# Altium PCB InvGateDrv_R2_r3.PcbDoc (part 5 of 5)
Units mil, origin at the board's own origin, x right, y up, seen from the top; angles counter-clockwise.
Board outline 6245 x 2850 mil, 4 copper layers (Top Layer, Power, Ground, Bottom Layer), stack 104.204 mil thick; 409 components, 181 nets, 1050 pads, 683 vias.
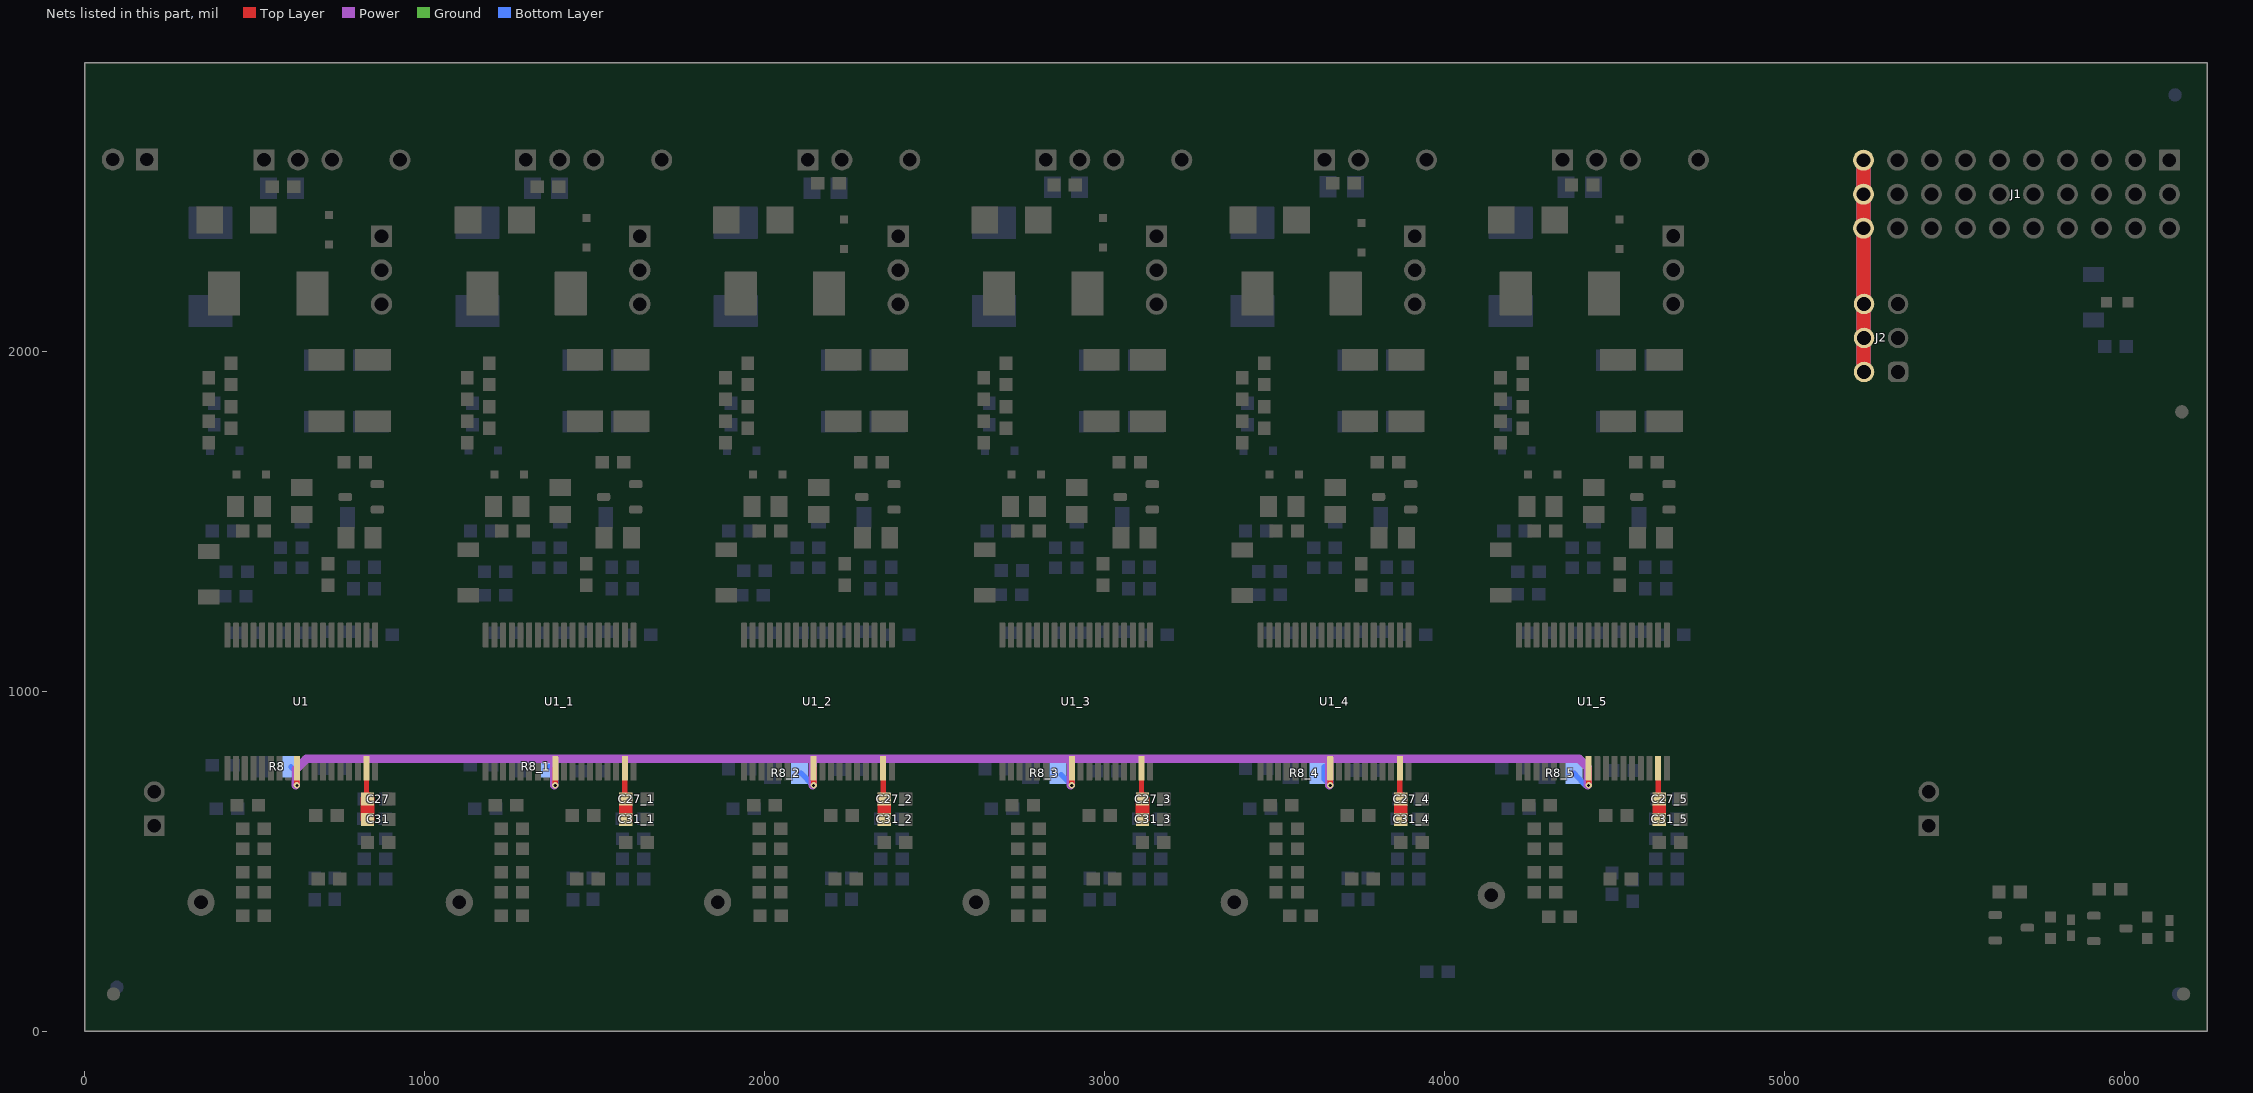
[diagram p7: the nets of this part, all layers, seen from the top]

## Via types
v1: diameter 19, hole 9, Top Layer to Bottom Layer, tented both sides, 617 vias
v2: diameter 20, hole 10, Top Layer to Bottom Layer, tented both sides, 66 vias

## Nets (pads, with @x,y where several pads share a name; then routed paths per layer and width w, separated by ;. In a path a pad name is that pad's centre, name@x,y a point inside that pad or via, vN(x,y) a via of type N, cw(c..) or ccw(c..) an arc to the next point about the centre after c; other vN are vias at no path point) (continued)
VCC1_3V3: R8.2 R8_1.2 R8_2.2 R8_3.2 R8_4.2 R8_5.2 U1.9 U1_1.9 U1_2.9 U1_3.9 U1_4.9 U1_5.9 | length 4872.4
  Top Layer w16: v1(624.57,723.98) U1.9@624.57,774.17 ; v1(1384.56,723.98) U1_1.9@1384.56,774.18 ; v1(2144.57,723.98) U1_2.9@2144.57,774.17 ; v1(2904,724) 2904,773.61 U1_3.9@2904.57,774.17 ; v1(3664.57,723.98) U1_4.9@3664.57,774.17 ; v1(4424.56,723.98) U1_5.9@4424.56,774.18
  Power w25: v1@621.78,723.98 621.78,771.39 652.13,801.73 1390.08,801.73 ; v1@1381.78,723.98 1381.78,793.43 1390.08,801.73 ; v1@2141.78,723.98 2141.78,793.44 2150.08,801.73 ; 2898.35,795 2901.78,791.56 v1@2901.78,723.98 ; 3658.35,795 3661.78,791.56 v1@3661.78,723.98 ; v1@4421.78,723.98 4421.78,776.96 4397.01,801.73 2150.08,801.73 ; 1390.08,801.73 2150.08,801.73
  Bottom Layer w16: R8.2@607.09,778.11 624.57,760.63 v1(624.57,723.98) ; R8_1.2@1367.08,778.11 1384.56,760.63 v1(1384.56,723.98) ; R8_2.2@2106.94,760 2142.96,723.98 v1(2144.57,723.98) ; R8_3.2@2873.07,755 2904.57,723.5 2904.07,724 v1(2904,724) ; R8_4.2@3647.09,778.11 3647.09,741.46 v1(3664.57,723.98) ; R8_5.2@4381.93,760 4407.08,731.89 4414.99,723.98 v1(4424.56,723.98)
VCC2: J1.28 J1.29 J1.30 J2.2 J2.4 J2.6 | length 2494.3
  Top Layer w40: J1.28@5233.35,2562.88 J1.29@5233.35,2462.88 J1.30@5233.35,2362.88 5233.35,1941.65 J2.2@5235,1940
  Power w40: J1.28@5233.35,2562.88 J1.29@5233.35,2462.88 J1.30@5233.35,2362.88 5233.35,1941.65 J2.2@5235,1940
  Ground w40: J1.28@5233.35,2562.88 J1.29@5233.35,2462.88 J1.30@5233.35,2362.88 5233.35,1941.65 J2.2@5235,1940
  Bottom Layer w40: J1.28@5233.35,2562.88 J1.29@5233.35,2462.88 J1.30@5233.35,2362.88 5233.35,1941.65 J2.2@5235,1940
VREG: C27.1 C31.1 U1.17 | length 151.8
  Top Layer w16: U1.17@829.29,774.17 829.29,686.57 C27.1@832.24,683.62
  Top Layer w40: C31.1@832.24,623.58 C27.1@832.24,683.62
VREG_1: C27_1.1 C31_1.1 U1_1.17 | length 151.8
  Top Layer w16: U1_1.17@1589.29,774.18 1589.29,686.58 C27_1.1@1592.24,683.62
  Top Layer w40: C31_1.1@1592.24,623.58 C27_1.1@1592.24,683.62
VREG_2: C27_2.1 C31_2.1 U1_2.17 | length 151.8
  Top Layer w16: U1_2.17@2349.29,774.17 2349.29,686.57 C27_2.1@2352.24,683.62
  Top Layer w40: C31_2.1@2352.24,623.58 C27_2.1@2352.24,683.62
VREG_3: C27_3.1 C31_3.1 U1_3.17 | length 151.8
  Top Layer w16: U1_3.17@3109.29,774.17 3109.29,686.57 C27_3.1@3112.24,683.62
  Top Layer w40: C31_3.1@3112.24,623.58 C27_3.1@3112.24,683.62
VREG_4: C27_4.1 C31_4.1 U1_4.17 | length 151.8
  Top Layer w16: U1_4.17@3869.29,774.17 3869.29,686.57 C27_4.1@3872.24,683.62
  Top Layer w40: C31_4.1@3872.24,623.58 C27_4.1@3872.24,683.62
VREG_5: C27_5.1 C31_5.1 U1_5.17 | length 151.8
  Top Layer w16: U1_5.17@4629.29,774.18 4629.29,686.58 C27_5.1@4632.24,683.63
  Top Layer w40: C31_5.1@4632.24,623.59 C27_5.1@4632.24,683.63
pads on no net: FID1.1 FID2.1 FID3.1 FID4.1 FID5.1 FID6.1 J1.1 J1.22 J1.23 J3.1 J3.2 J6.1 J6.2 R22_1.2 R22_2.2 R22_3.2 R22_4.2 R22_5.2 R25_1.2 R25_2.2 R25_3.2 R25_4.2 R25_5.2 U1.2 U1.3 U1.4 U1.5 U1_1.2 U1_1.3 U1_1.4 U1_1.5 U1_2.2 U1_2.3 U1_2.4 U1_2.5 U1_3.2 U1_3.3 U1_3.4 U1_3.5 U1_4.2 U1_4.3 U1_4.4 U1_4.5 U1_5.2 U1_5.3 U1_5.4 U1_5.5

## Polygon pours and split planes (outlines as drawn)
GND on Ground "GROUND_GND_P118" (solid, remove dead copper, pour order 118): 5885.83,2690 5985.83,2590 5985.83,421.52 5694.31,130 4825.83,130 4639.02,316.8 4639.66,704.64 4708.46,778.51 5177.67,778.5 5224.17,825 5224.17,1844 5245.98,1865.81 5360,1865.81 5385,1890 5385,2610 5465,2690
GND on Ground "GROUND_GND_P002" (solid, remove dead copper, pour order 2): 893.27,792.87 932.64,753.5 932.64,94.06 873.58,35 381.46,35 332.24,84.21 332.24,753.5 371.61,792.87
GND on Ground "GROUND_GND_P022" (solid, remove dead copper, pour order 22): 1653.26,792.88 1692.63,753.51 1692.63,94.06 1633.58,35 1141.45,35 1092.24,84.21 1092.24,753.51 1131.61,792.88
GND on Ground "GROUND_GND_P038" (solid, remove dead copper, pour order 38): 2413.27,792.87 2452.64,753.5 2452.64,94.05 2393.58,35 1901.46,35 1852.24,84.21 1852.24,753.5 1891.61,792.87
GND on Ground "GROUND_GND_P054" (solid, remove dead copper, pour order 54): 3173.27,792.87 3212.64,753.5 3212.64,94.06 3153.58,35 2661.46,35 2612.24,84.21 2612.24,753.5 2651.61,792.87
GND on Ground "GROUND_GND_P086" (solid, remove dead copper, pour order 86): 3933.27,792.87 3972.64,753.5 3972.64,94.05 3913.58,35 3421.46,35 3372.24,84.21 3372.24,753.5 3411.61,792.87
GND on Ground "GROUND_GND_P102" (solid, remove dead copper, pour order 102): 4693.26,792.88 4732.63,753.51 4732.63,94.06 4673.58,35 4181.45,35 4132.24,84.22 4132.24,753.51 4171.61,792.88
no net on Ground "GROUND_NONET_P100" (solid, remove dead copper, pour order 100): 4693.26,1127.52
ISO_GND_5 on Ground "GROUND_ISO_GND_5_P098" (solid, remove dead copper, pour order 98): 4210.18,1137.37 4667.81,1137.37 4728.62,1198.18 4728.62,2332.33 4673.58,2387.37 4201.14,2387.37 4142.08,2328.31 4142.08,1197.56
no net on Ground "GROUND_NONET_P084" (solid, remove dead copper, pour order 84): 3933.27,1127.52
ISO_GND_4 on Ground "GROUND_ISO_GND_4_P082" (solid, remove dead copper, pour order 82): 3450.18,1137.36 3907.81,1137.36 3968.62,1198.17 3968.62,2332.32 3913.58,2387.36 3441.14,2387.36 3382.09,2328.31 3382.09,1197.56
no net on Ground "GROUND_NONET_P052" (solid, remove dead copper, pour order 52): 3173.27,1127.52
ISO_GND_3 on Ground "GROUND_ISO_GND_3_P050" (solid, remove dead copper, pour order 50): 2690.18,1137.36 3147.81,1137.36 3208.62,1198.17 3208.62,2332.32 3153.58,2387.36 2681.14,2387.36 2622.09,2328.31 2622.09,1197.56
no net on Ground "GROUND_NONET_P036" (solid, remove dead copper, pour order 36): 2413.27,1127.52
ISO_GND_2 on Ground "GROUND_ISO_GND_2_P034" (solid, remove dead copper, pour order 34): 1930.18,1137.36 2387.81,1137.36 2448.62,1198.17 2448.62,2332.32 2393.58,2387.36 1921.14,2387.36 1862.09,2328.31 1862.09,1197.56
no net on Ground "GROUND_NONET_P020" (solid, remove dead copper, pour order 20): 1653.26,1127.52
ISO_GND_1 on Ground "GROUND_ISO_GND_1_P018" (solid, remove dead copper, pour order 18): 1170.17,1137.36 1627.81,1137.36 1688.62,1198.17 1688.62,2332.33 1633.58,2387.36 1161.14,2387.36 1102.08,2328.31 1102.08,1197.56
ISO_GND on Ground "GROUND_ISO_GND_P014" (solid, remove dead copper, pour order 14): 410.18,1137.36 867.81,1137.36 928.62,1198.17 928.62,2332.32 873.58,2387.36 401.14,2387.36 342.09,2328.31 342.09,1197.56
no net on Ground "GROUND_NONET_P012" (solid, remove dead copper, pour order 12): 893.27,1127.52
ISO_GND_5 on Top Layer "TOP_LAYER_ISO_GND_5_P144" (solid, remove dead copper, pour order 144): 4546.22,1232.88 4553.34,1240 4603.34,1240 4613.34,1230 4612.56,1229.22 4612.56,1143.86 4603.7,1135 4553.34,1135 4546.22,1142.13
ISO_GND_4 on Top Layer "TOP_LAYER_ISO_GND_4_P142" (solid, remove dead copper, pour order 142): 3786.22,1232.87 3793.35,1240 3843.35,1240 3853.35,1230 3852.56,1229.21 3852.56,1143.86 3843.7,1135 3793.35,1135 3786.22,1142.13
ISO_GND_3 on Top Layer "TOP_LAYER_ISO_GND_3_P140" (solid, remove dead copper, pour order 140): 3026.22,1232.87 3033.35,1240 3083.35,1240 3093.35,1230 3092.56,1229.21 3092.56,1143.86 3083.7,1135 3033.35,1135 3026.22,1142.13
ISO_GND_2 on Top Layer "TOP_LAYER_ISO_GND_2_P138" (solid, remove dead copper, pour order 138): 2266.22,1232.87 2273.35,1240 2323.35,1240 2333.35,1230 2332.56,1229.21 2332.56,1143.86 2323.7,1135 2273.35,1135 2266.22,1142.13
ISO_GND_1 on Top Layer "TOP_LAYER_ISO_GND_1_P136" (solid, remove dead copper, pour order 136): 1506.22,1232.88 1513.34,1240 1563.34,1240 1573.34,1230 1572.55,1229.21 1572.55,1143.86 1563.7,1135 1513.34,1135 1506.22,1142.13
ISO_GND on Top Layer "TOP_LAYER_ISO_GND_P134" (solid, remove dead copper, pour order 134): 746.22,1232.87 753.35,1240 803.35,1240 813.35,1230 812.56,1229.21 812.56,1143.86 803.7,1135 753.35,1135 746.22,1142.13
VCC1 on Top Layer "TOP_LAYER_VCC1_P132" (solid, remove dead copper, pour order 132): 4395.98,361.93 4417.4,383.35 4417.4,449.22 4440.12,471.93 4632.75,471.93 4657.4,447.29 4657.4,336.93 4628.97,308.51 4362.24,308.51 4352.4,318.35 4352.4,356.93 4357.4,361.93
VCC1 on Top Layer "TOP_LAYER_VCC1_P128" (solid, remove dead copper, pour order 128): 3633.19,365 3654.61,386.42 3654.61,452.28 3677.32,475 3869.96,475 3894.61,450.35 3894.61,340 3866.18,311.57 3599.45,311.57 3589.61,321.42 3589.61,360 3594.61,365
VCC1 on Top Layer "TOP_LAYER_VCC1_P126" (solid, remove dead copper, pour order 126): 2831.93,365 2853.35,386.42 2853.35,452.28 2876.06,475 3068.7,475 3093.35,450.35 3093.35,340 3064.92,311.57 2798.19,311.57 2788.35,321.42 2788.35,360 2793.35,365
VCC1 on Top Layer "TOP_LAYER_VCC1_P124" (solid, remove dead copper, pour order 124): 2071.93,365 2093.35,386.42 2093.35,452.28 2116.06,475 2308.7,475 2333.35,450.35 2333.35,340 2304.92,311.57 2038.19,311.57 2028.35,321.42 2028.35,360 2033.35,365
VCC1 on Top Layer "TOP_LAYER_VCC1_P122" (solid, remove dead copper, pour order 122): 1311.92,365 1333.34,386.42 1333.34,452.29 1356.06,475 1548.7,475 1573.34,450.36 1573.34,340 1544.92,311.58 1278.18,311.58 1268.34,321.42 1268.34,360 1273.34,365
VCC1 on Top Layer "TOP_LAYER_VCC1_P120" (solid, remove dead copper, pour order 120): 551.93,365 573.35,386.42 573.35,452.28 596.06,475 788.7,475 813.35,450.35 813.35,340 784.92,311.57 518.19,311.57 508.35,321.42 508.35,360 513.35,365
VCC1 on Top Layer "Top Layer-VCC1" (solid, pour order 114): 5989.15,279.2 6013.35,255 6013.35,240 5993.35,220 5553.35,220 5538.35,235 5538.35,255 5562.55,279.2
GND on Top Layer "TOP_LAYER_GND_P110" (solid, pour order 110): 4703.11,812.56 4732.63,783.04 4732.63,526.15 4713.93,507.45 4684.41,507.45 4673.58,518.27 4673.58,723.98 4653.89,743.67 4653.89,805.28 4661.18,812.56
GND on Top Layer "TOP_LAYER_GND_P108" (solid, remove dead copper, pour order 108): 4208.34,810.3 4212.26,810.3 4159.46,810.3 4132.24,783.08 4132.24,438.55 4171.61,399.18 4270.04,399.18 4289.72,418.86 4289.72,785.6 4264.72,810.6 4161.77,810.3
ISO_VCC_5 on Top Layer "TOP_LAYER_ISO_VCC_5_P106" (solid, remove dead copper, pour order 106): 4250.35,1292.58 4228.8,1315.54 4142.81,1315.54 4132.24,1307.72 4132.24,1157.05 4160.22,1129.49 4235.59,1129.49 4250.35,1144.26
ISO_VEE_5 on Top Layer "TOP_LAYER_ISO_VEE_5_P104" (solid, pour order 104): 4682.44,1364.89 4652.91,1335.36 4652.91,1146.78 4661.18,1138.51 4713.93,1138.51 4728.34,1152.92 4728.34,1349.49 4712.95,1364.89
GND on Top Layer "TOP_LAYER_GND_P094" (solid, pour order 94): 3943.11,812.56 3972.64,783.03 3972.64,526.14 3953.94,507.44 3924.41,507.44 3913.58,518.27 3913.58,723.98 3893.9,743.66 3893.9,805.28 3901.18,812.56
GND on Top Layer "TOP_LAYER_GND_P092" (solid, remove dead copper, pour order 92): 3448.35,810.3 3452.26,810.3 3399.47,810.3 3372.24,783.08 3372.24,438.54 3411.61,399.17 3510.04,399.17 3529.72,418.86 3529.72,785.59 3504.72,810.59 3401.77,810.3
ISO_VCC_4 on Top Layer "TOP_LAYER_ISO_VCC_4_P090" (solid, remove dead copper, pour order 90): 3490.35,1292.58 3468.8,1315.53 3389.02,1315.53 3372.24,1303.13 3372.24,1157.05 3400.22,1129.49 3475.59,1129.49 3490.35,1144.25
ISO_VEE_4 on Top Layer "TOP_LAYER_ISO_VEE_4_P088" (solid, pour order 88): 3922.44,1364.88 3892.91,1335.35 3892.91,1146.77 3901.18,1138.5 3953.94,1138.5 3968.35,1152.91 3968.35,1349.49 3952.95,1364.88
GND on Top Layer "TOP_LAYER_GND_P062" (solid, pour order 62): 3183.11,812.56 3212.64,783.03 3212.64,526.14 3193.94,507.44 3164.41,507.44 3153.58,518.27 3153.58,723.98 3133.9,743.66 3133.9,805.28 3141.18,812.56
GND on Top Layer "TOP_LAYER_GND_P060" (solid, remove dead copper, pour order 60): 2688.35,810.3 2692.26,810.3 2639.47,810.3 2612.24,783.08 2612.24,438.54 2651.61,399.17 2750.04,399.17 2769.72,418.86 2769.72,785.59 2744.72,810.59 2641.77,810.3
ISO_VCC_3 on Top Layer "TOP_LAYER_ISO_VCC_3_P058" (solid, remove dead copper, pour order 58): 2730.35,1292.58 2708.8,1315.54 2622.81,1315.54 2612.24,1307.72 2612.24,1157.05 2640.22,1129.49 2715.59,1129.49 2730.35,1144.25
ISO_VEE_3 on Top Layer "TOP_LAYER_ISO_VEE_3_P056" (solid, pour order 56): 3162.44,1364.88 3132.91,1335.35 3132.91,1146.77 3141.18,1138.5 3193.94,1138.5 3208.35,1152.91 3208.35,1349.49 3192.95,1364.88
GND on Top Layer "TOP_LAYER_GND_P046" (solid, pour order 46): 2423.11,812.56 2452.64,783.03 2452.64,526.14 2433.94,507.44 2404.41,507.44 2393.58,518.27 2393.58,723.98 2373.9,743.66 2373.9,805.28 2381.18,812.56
GND on Top Layer "TOP_LAYER_GND_P044" (solid, remove dead copper, pour order 44): 1928.35,810.3 1932.26,810.3 1879.47,810.3 1852.24,783.08 1852.24,438.54 1891.61,399.17 1990.04,399.17 2009.72,418.86 2009.72,785.59 1984.72,810.59 1881.77,810.3
ISO_VCC_2 on Top Layer "TOP_LAYER_ISO_VCC_2_P042" (solid, remove dead copper, pour order 42): 1970.35,1292.58 1948.8,1315.53 1880.22,1315.53 1852.24,1294.84 1852.24,1157.05 1880.22,1129.49 1955.59,1129.49 1970.35,1144.25
ISO_VEE_2 on Top Layer "TOP_LAYER_ISO_VEE_2_P040" (solid, pour order 40): 2402.44,1364.88 2372.91,1335.35 2372.91,1146.77 2381.18,1138.5 2433.94,1138.5 2448.35,1152.91 2448.35,1349.49 2432.95,1364.88
GND on Top Layer "TOP_LAYER_GND_P030" (solid, pour order 30): 1663.11,812.56 1692.63,783.03 1692.63,526.14 1673.93,507.44 1644.41,507.44 1633.58,518.27 1633.58,723.98 1613.89,743.66 1613.89,805.28 1621.18,812.56
GND on Top Layer "TOP_LAYER_GND_P028" (solid, remove dead copper, pour order 28): 1157.7,810.3 1172.26,810.3 1119.46,810.3 1092.24,783.08 1092.24,438.55 1131.61,399.18 1230.04,399.18 1249.72,418.86 1249.72,785.59 1224.72,810.59 1121.77,810.3
ISO_VCC_1 on Top Layer "TOP_LAYER_ISO_VCC_1_P026" (solid, remove dead copper, pour order 26): 1210.35,1292.58 1188.79,1315.54 1109.02,1315.54 1092.24,1303.13 1092.24,1157.05 1120.22,1129.49 1195.59,1129.49 1210.35,1144.25
ISO_VEE_1 on Top Layer "TOP_LAYER_ISO_VEE_1_P024" (solid, pour order 24): 1642.44,1364.88 1612.91,1335.36 1612.91,1146.77 1621.18,1138.51 1673.93,1138.51 1688.34,1152.92 1688.34,1349.49 1672.95,1364.88
ISO_VEE on Top Layer "TOP_LAYER_ISO_VEE_P016" (solid, pour order 16): 882.44,1364.88 852.91,1335.35 852.91,1146.77 861.18,1138.5 913.94,1138.5 928.35,1152.91 928.35,1349.49 912.95,1364.88
ISO_VCC on Top Layer "TOP_LAYER_ISO_VCC_P010" (solid, remove dead copper, pour order 10): 450.35,1292.58 428.8,1315.54 360.22,1315.54 332.24,1294.84 332.24,1157.05 360.22,1129.49 435.59,1129.49 450.35,1144.25
GND on Top Layer "TOP_LAYER_GND_P006" (solid, remove dead copper, pour order 6): 408.35,810.3 412.26,810.3 359.47,810.3 332.24,783.08 332.24,438.54 371.61,399.17 470.04,399.17 489.72,418.86 489.72,785.59 464.72,810.59 361.77,810.3
GND on Top Layer "TOP_LAYER_GND_P004" (solid, pour order 4): 903.11,812.56 932.64,783.03 932.64,526.14 913.94,507.44 884.41,507.44 873.58,518.27 873.58,723.98 853.9,743.66 853.9,805.28 861.18,812.56
no net on Bottom Layer "Bottom Layer-No Net" (solid, pour order 116): 5463.35,2665
GND on Bottom Layer "BOTTOM_LAYER_GND_P112" (solid, remove dead copper, pour order 112): 4693.26,792.88 4732.63,753.51 4732.63,94.06 4673.58,35 4181.45,35 4132.24,84.22 4132.24,776.16 4148.96,792.88
GND on Bottom Layer "BOTTOM_LAYER_GND_P096" (solid, remove dead copper, pour order 96): 3933.27,792.87 3972.64,753.5 3972.64,94.05 3913.58,35 3421.46,35 3372.24,84.21 3372.24,767.24 3397.87,792.87
GND on Bottom Layer "BOTTOM_LAYER_GND_P064" (solid, remove dead copper, pour order 64): 3173.27,792.87 3212.64,753.5 3212.64,94.06 3153.58,35 2661.46,35 2612.24,84.21 2612.24,771.06 2634.06,792.87
GND on Bottom Layer "BOTTOM_LAYER_GND_P048" (solid, remove dead copper, pour order 48): 2413.27,792.87 2452.64,753.5 2452.64,94.05 2393.58,35 1901.46,35 1852.24,84.21 1852.24,767.24 1877.87,792.87
GND on Bottom Layer "BOTTOM_LAYER_GND_P032" (solid, remove dead copper, pour order 32): 1644.4,801.73 1692.63,753.51 1692.63,94.06 1633.58,35 1141.45,35 1092.24,84.21 1092.24,777.24 1116.73,801.73
GND on Bottom Layer "BOTTOM_LAYER_GND_P008" (solid, remove dead copper, pour order 8): 886.14,800 932.64,753.5 932.64,94.06 873.58,35 381.46,35 332.24,84.21 332.24,772.24 360,800

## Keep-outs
Keep-Out Layer:
  text ".Layer_Name" at 577,-858.49 h60

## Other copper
Top Layer:
  text ".Layer_Name" at 567,-858.49 h60
Power:
  text ".Layer_Name" at 577,-858.49 h60
Ground:
  text ".Layer_Name" at 572,-858.49 h60
Bottom Layer:
  text ".Layer_Name" at 577,-858.49 h60

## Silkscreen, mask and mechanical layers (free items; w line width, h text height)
Top Overlay:
  lines w20: 50,960 4975,960 4975,2810
  text "EGVDD C" at 679.91,2466.93 h40
  text "EG C" at 2284.66,2465 h40
  text "EGVDD C" at 4518.35,2462.8 h40
  text "EGVDD C" at 3005.84,2460.07 h40
  text "EG C" at 3810,2460 h40
  text "EGVDD C" at 1482.76,2458.94 h40
  text "GND A1" at 33.03,2449.36 h40
  text "LOW VOLTAGE" at 5056.11,2277.54 h80 r90
  text "HIGH VOLTAGE" at 4941.48,2269.81 h80 r90
  text "VEE GND VCC" at 3270,2010 h40 r90
  text "VEE GND VCC" at 4035,2010 h40 r90
  text "VEE GND VCC" at 4795,2010 h40 r90
  text "VEE GND VCC" at 1000,2005 h40 r90
  text "VEE GND VCC" at 2520,2005 h40 r90
  text "VEE GND VCC" at 1755,2002.44 h40 r90
  text "VCC1 on" at 6140,1962.75 h40 r90
  text "VCC2 GND" at 5114,1822.54 h40
  text "Danger High Voltage" at 195.5,1420 h110 r90
  text "LOW VOLTAGE" at 5055,1010 h80 r90
  text "HIGH VOLTAGE" at 4938.48,1005.87 h80 r90
  text "HIGH VOLTAGE" at 52.71,996.52 h80
  text "LOW VOLTAGE" at 53.09,877 h80
  text "'.PRJ_Number'.PCB_Rev" at 5813,838.9 h70 r90
  text "Inverter Gate Driver" at 5732,833.9 h120 r90
  text "FLT_HS" at 5795.16,410 h40 r90
  text "FLT_LS" at 6086.06,405 h40 r90
  text "CL" at 594.73,120 h80
  text "CH" at 1346.38,119 h80
  text "BL" at 2107.38,115 h80
  text "BH" at 2868.61,112 h80
  text "AL" at 3627.38,110 h80
  text "AH" at 4388.38,110 h80
  text ".Layer_Name" at 577,-858.49 h35
Bottom Overlay:
  lines w20: 50,960 131.36,960 ; 275,960 4975,960 4975,2810
  text "C   E G VDD" at 1707.67,2655 h40
  text "C    E G" at 2433.82,2655 h40
  text "C   E G VDD" at 3227.67,2655 h40
  text "C   E G VDD" at 935.35,2650 h40
  text "C    E G" at 3955,2650 h40
  text "C   E G VDD" at 4747.67,2650 h40
  text "LOW VOLTAGE" at 5053.11,2303.78 h80 r90
  text "HIGH VOLTAGE" at 4938.48,2296.05 h80 r90
  text "Danger High Voltage" at 123,1465 h110 r270
  text "Mech Sup Only" at 5350,1045.37 h30 r90
  text "HIGH VOLTAGE" at 952.31,996.52 h80
  text "HIGH VOLTAGE" at 4233.6,996.52 h80
  text "LOW VOLTAGE" at 960,877 h80
  text "LOW VOLTAGE" at 4240.57,875 h80
  text "Mech Sup Only" at 131.36,850 h30 r90
  text "CL" at 762.1,117.72 h80
  text "CH" at 1513.74,116.72 h80
  text "BL" at 2274.74,112.72 h80
  text "BH" at 3035.98,109.72 h80
  text "AL" at 3794.74,107.72 h80
  text "AH" at 4555.74,107.72 h80
  text ".Layer_Name" at 577,-858.49 h35
Top Paste:
  text ".Layer_Name" at 577,-858.49 h60
Bottom Paste:
  text ".Layer_Name" at 577,-858.49 h60
Top Solder:
  text ".Layer_Name" at 577,-858.49 h60
  text ".Layer_Name" at 577,-858.49 h60
Bottom Solder:
  text ".Layer_Name" at 577,-858.49 h60
Drill Guide:
  text ".Layer_Name" at 577,-858.49 h60
M1 Board Outline:
  the board outline again, w10
  text ".Layer_Name" at 577,-858.49 h60
M2 Board Dimensions:
  rectangle: 0,-275 125,-150
  rectangle: 125,-400 500,-275
  lines w7: 0,-275 1000,-275 ; 125,-400 125,-150 ; 250,-400 250,-150 ; 500,-400 500,-150 ; 750,-400 750,-150 ; 0,-400 1000,-400 1000,-150 0,-150 0,-400
  text ".Layer_Name" at 577,-858.49 h60
M3 3D STEP Top:
  text ".Layer_Name" at 577,-858.49 h60
M4 3D STEP Bottom:
  text ".Layer_Name" at 577,-858.49 h60
M5 Assembly Top:
  lines w10: -292,-930.17 6308,-930.17 ; -292,-726.83 6310,-726.83 ; -292,-523.5 -292,-1133.5 3713,-1133.5 6310,-1133.5 6310,-523.5 -291.5,-523.5 -291.5,-1133.5 1284,-1133.5 ; 2173,-1133.5 2173,-523.5 ; 3440,-726.83 3440,-523.5 ; 4280,-726.83 4280,-523.5 ; 4902,-1140 4902,-937.17
  text "COMPONENTS MARKED 'DNP' SHOULD NOT BE POPULATED." at 1153.5,-318.5 h60
  text "ASSEMBLY VARIANT:" at 1153,-434 h60
  text ".VariantName" at 2189,-434 h60
  text "PCB VIEWED FROM TOP SIDE" at -228.5,-655.67 h60
  text "BOARD #:" at 2248,-655.67 h60
  text ".PRJ_Number" at 2793.5,-655.67 h60
  text "REV:" at 3638,-655.67 h60
  text ".PCB_Rev" at 3929.5,-655.67 h60
  text "SVN REV:" at 4476,-655.67 h60
  text ".VersionControl_RevNumber" at 4982,-655.67 h60
  text "TID #:" at 2248,-859 h60
  text ".TID" at 2793.5,-859 h60
  text "PLOT NAME =" at -228.5,-1064.34 h60
  text ".plot_File_Name" at 577,-1064.34 h60
  text "GENERATED    :" at 2250,-1064.34 h60
  text ".Print_Date" at 3119.5,-1064.34 h60
  text ".Print_Time" at 3848.5,-1064.34 h60
  text "TEXAS INSTRUMENTS" at 5113,-1064.34 h60
M6 Assembly Bottom:
  lines w10: -292.5,-727.33 6309.5,-727.33 ; -290.5,-930.67 6309.5,-930.67 ; 1115.5,-1140.5 1115.5,-937.67 ; 1737.5,-727.33 1737.5,-524 ; 2577.5,-727.33 2577.5,-524 ; 3844.5,-1134 3844.5,-524 ; 4733.5,-1134 6309,-1134 6309,-524 -292.5,-524 -292.5,-1134 2304.5,-1134 6309.5,-1134 6309.5,-524
  text "COMPONENTS MARKED 'DNP' SHOULD NOT BE POPULATED." at 6102,-318 h60
  text ".VariantName" at 5058,-434 h60
  text "ASSEMBLY VARIANT:" at 6097,-434 h60
  text ".VersionControl_RevNumber" at 1035.5,-656.17 h60
  text "SVN REV:" at 1541.5,-656.17 h60
  text ".PCB_Rev" at 2088,-656.17 h60
  text "REV:" at 2379.5,-656.17 h60
  text ".PRJ_Number" at 3224,-656.17 h60
  text "BOARD #:" at 3769.5,-656.17 h60
  text "PCB VIEWED FROM BOTTOM SIDE" at 6246,-656.17 h60
  text ".TID" at 3224,-859.5 h60
  text "TID #:" at 3769.5,-859.5 h60
  text "TEXAS INSTRUMENTS" at 904.5,-1064.84 h60
  text ".Print_Time" at 2169,-1064.84 h60
  text ".Print_Date" at 2898,-1064.84 h60
  text "GENERATED    :" at 3767.5,-1064.84 h60
  text ".plot_File_Name" at 5440.5,-1064.84 h60
  text "PLOT NAME =" at 6246,-1064.84 h60
M9 Title Sheet:
  drawing of 57 lines, arcs and shapes, not listed
  text "1" at 739.84,8036.5 h70
  text "2" at 3235.5,8036.5 h70
  text "3" at 5724.84,8036.5 h70
  text "4" at 8231.51,8036.5 h70
  text "5" at 10730.5,8036.5 h70
  text "6" at 13235.5,8036.5 h70
  text "A" at -416.5,6893.5 h70
  text "A" at 14383.5,6893.5 h70
  text "B" at -416.5,4513.5 h70
  text "B" at 14383.5,4513.5 h70
  text "C" at -416.5,2138.5 h70
  text "C" at 14383.5,2138.5 h70
  text "PROJECT TITLE:" at 11343.5,277.5 h45
  text ".PRJ_Title" at 11393.5,144.17 h70
  text "DESIGNED FOR:" at 11343.5,-23.5 h45
  text ".PRJ_Customer" at 11393.5,-163.5 h70
  text "D" at -416.5,-231.5 h70
  text "D" at 14383.5,-231.5 h70
  text "FILE NAME:" at 11343.5,-323.5 h45
  text ".PCB_File_Name_No_Path" at 11393.5,-443.5 h70
  text "Texas Instruments (TI) and/or its licensors do not warrant the accuracy or completeness of this specification" at 6374,-605.34 h45
  text "ENGINEER:" at 11343.5,-613.5 h45
  text "LAYOUT BY:" at 12848.5,-613.5 h45
  text "or any information contained therein. TI and/or its licensors do not warrant that this design will meet" at 6329.01,-718 h45
  text ".PRJ_Engineer" at 11393.5,-768.49 h70
  text ".PCB_Layout" at 12899,-768.49 h70
  text "the specifications, will be suitable for your application or fit for any particular purpose, or will operate in" at 6329.01,-830.67 h45
  text ".Layer_Name" at 577,-858.49 h60
  text "ALTIUM DESIGNER VERSION:" at 12848.5,-923.5 h45
  text "an implementation. TI and/or its licensors do not warrant that the design is production worthy. You should" at 6329.01,-943.33 h45
  text "completely validate and test your design implementation to confirm the system functionality for your application." at 6374,-1056 h45
  text ".print_Scale" at 11393.5,-1056.83 h70
  text ".Application_BuildNumber" at 12899,-1056.83 h70
  text "1" at 739.84,-1263.5 h70
  text "2" at 3235.5,-1263.5 h70
  text "3" at 5724.84,-1263.5 h70
  text "4" at 8231.51,-1263.5 h70
  text "5" at 10730.5,-1263.5 h70
  text "6" at 13235.5,-1263.5 h70
M10 Fab Notes:
  drawing of 189 lines, arcs and shapes, not listed
  text "DESIGN INFORMATION" at 12382.02,6356.17 h60
  text "MIN. TRACK WIDTH:" at 11737.46,6224.05 h60
  text "8" at 12833.7,6224.05 h60
  text "MIL" at 12988.46,6224.05 h60
  text "MIN. CLEARANCE:" at 11737.46,6099.92 h60
  text "0.2" at 12773.7,6099.93 h60
  text "mm" at 12988.46,6099.92 h60
  text "MIN. VIA PAD SIZE:" at 11737.46,5975.8 h60
  text "24" at 12803.71,5975.8 h60
  text "MIL" at 12988.46,5975.8 h60
  text "0.05mm (2MIL)" at 12432.46,5845.9 h60
  text "MINIMUM ANNULAR RING" at 11408.23,5837.67 h60
  text "EXTERNAL" at 13140.46,5837.67 h60
  text "PER" at 11608.23,5727.55 h60
  text "IPC-D-275 CLASS 2 LEVEL C" at 11828.23,5727.54 h60
  text "MIL, HOLES" at 13316.46,5627.07 h60
  text "+/-" at 12924,5618.48 h60
  text "+/-" at 13778,5618.48 h60
  text "REGISTRATION TOLERANCES:" at 11408.23,5617.42 h60
  text "METAL" at 12608,5617.42 h60
  text "5" at 13184.2,5617.42 h60
  text "3" at 14017.2,5617.42 h60
  text "MIL" at 14133.46,5617.42 h60
  text "HOLE SIZE TOLERANCE (UNLESS OTHERWISE SPECIFIED):" at 11408.23,5519.1 h60
  text "+/-" at 13778,5516.23 h60
  text "3" at 14017.2,5515.17 h60
  text "MIL" at 14133.46,5515.17 h60
  text "MATERIAL:" at 11333.46,5377.52 h60
  text "FR-4 High Tg" at 12319.9,5249 h60
  text "X" at 12175.46,5241.01 h60
  text "FR-408" at 11754.46,5236.49 h60
  text "OTHER" at 13242.46,5236.49 h60
  text "62 MIL (1.6mm) +/-10%" at 12074.56,5093.46 h60
  text "X" at 11954.46,5091.01 h60
  text "THICKNESS:" at 11408.23,5085.24 h60
  text "OTHER" at 13359.46,5085.24 h60
  text "TOLERANCE:" at 11408.23,4946.92 h60
  text "X" at 12256.46,4946.92 h60
  text "ANSI IPC-6012 TYPE 3 CLASS 2" at 12434.48,4946.92 h60
  text "OTHER +/-" at 12434.46,4802.73 h60
  text "BOW & TWIST:" at 11408.23,4657.54 h60
  text "X" at 12256.46,4657.54 h60
  text "ANSI IPC-6012 TYPE 3 CLASS 2" at 12434.48,4657.54 h60
  text "OTHER +/-" at 12434.46,4510.85 h60
  text "DRILLING:" at 11333.46,4380.23 h60
  text "NC_DRILL FILES" at 13094.46,4275.04 h60
  text "REFERENCE:" at 11408.23,4271.1 h60
  text "X" at 12065.46,4271.01 h60
  text "AS SHOWN" at 12243.46,4271.1 h60
  text "X" at 12966.46,4271.1 h60
  text "OTHER" at 13392.46,4128.85 h60
  text "PTH COPPER THICKNESS:" at 11407.91,4125.32 h60
  text "X" at 12547.14,4125.32 h60
  text "20-30 um" at 12675.14,4125.32 h60
  text "BOARD FINISH:" at 11333.46,3977.73 h60
  text "SILKSCREEN:" at 11488.68,3867.6 h60
  text "X" at 12446.46,3867.6 h60
  text "TOP" at 12563.46,3867.6 h60
  text "X" at 12956.46,3867.6 h60
  text "BOTTOM" at 13074.46,3867.6 h60
  text "SILKSCREEN COLOR:" at 11488.68,3712.41 h60
  text "X" at 12445.46,3712.41 h60
  text "WHITE" at 12563.46,3712.41 h60
  text "OTHER" at 13074.46,3712.41 h60
  text "X" at 12576.46,3568.96 h60
  text "GREEN" at 12694.46,3568.96 h60
  text "OTHER" at 13312.46,3568.96 h60
  text "SOLDER RESIST COLOR:" at 11488.68,3562.1 h60
  text "X" at 12576.46,3414.71 h60
  text "MATTE" at 12694.46,3414.71 h60
  text "SEMI-GLOSS" at 13312,3414.07 h60
  text "IMMERSION GOLD (ENIG)" at 12394.46,3241.94 h60
  text "ENEPIG" at 13732,3234.72 h60
  text "SURFACE FINISH:" at 11333.46,3233.72 h60
  text "X" at 12216.46,3233.72 h60
  text "IMM. TIN/SILVER OR EQUIV" at 11663,3096.4 h60
  text "OTHER" at 13094.46,3092.47 h60
  text "X" at 12217,2938 h60
  text "ARRAY/PANEL:" at 11333.46,2937.09 h60
  text "CUT AND TRIM PER M1 BOARD OUTLINE" at 12394.46,2928.87 h60
  text "N.C. ROUTE" at 12394.46,2792.9 h60
  text "V. SCORE" at 13260.46,2792.9 h60
  text "CERTIFICATION:" at 11333.46,2663.77 h60
  text "MATERIALS AND WORKMANSHIP FOR ALL PCBS" at 12058.46,2663.77 h60
  text "TO MEET OR EXCEED THE REQUIREMENTS OF:" at 12058.46,2569.71 h60
  text "X" at 11695.97,2441.08 h60
  text "ANSI IPC-A-600F CLASS ->" at 11823.96,2441.08 h60
  text "X" at 13471.97,2441.08 h60
  text "2" at 13581.96,2441.08 h60
  text "1" at 13266.96,2439.58 h60
  text "3" at 13935.96,2439.58 h60
  text "X" at 12507.97,2293.39 h60
  text "RoHS" at 12635.96,2293.39 h60
  text "OTHER" at 13280.36,2293.39 h60
  text "PER ORDER" at 13677.42,2293.39 h60
  text "ALL BOARDS MUST MEET OR EXCEED UL94-V0 REQUIREMENTS." at 11361,2139.57 h60
  text "PCB MUST BEAR THE UL94V-0 UL REGISTERED MATERIAL ID NUMBER" at 11361,2023.5 h60
  text "ADDITIONAL REQUIREMENTS:" at 11333.46,1854.08 h60
  text "MICROSECTION:" at 11408.23,1746.95 h60
  text "YES" at 12313.96,1746.95 h60
  text "REQUIRED" at 13175.46,1602.62 h60
  text "BARE BOARD ELEC. TEST:" at 11408.23,1599.76 h60
  text "NONE" at 12713.96,1599.76 h60
  text "X" at 13057.46,1599.76 h60
  text "PER ORDER" at 13767.46,1599.76 h60
  text "XX MIL VIAS REQUIRE NON-CONDUCTIVE FILL AND PLANARIZE" at 11576.38,1394.82 h59
  text "XX MIL VIAS REQUIRE CONDUCTIVE FILL AND PLANARIZE" at 11584.38,1290.84 h60
  text "OUTER XX MIL TRACES REQUIRE 50 OHM SINGLE-ENDED IMPEDANCE" at 11583.39,1127.46 h58
  text "LAYER 2 & 3 (INNER LAYERS) XX MIL WIDE, XX MIL SPACE / TRACES REQUIRE 100 OHM DIFFERENTIAL IMPEDANCE" at 11575.39,891.74 h60
  text ".Layer_Name" at 577,-858.49 h60
M11 Gerber Information:
  lines w10: -292,-930.17 6308,-930.17 ; -292,-726.83 6310,-726.83 ; -292,-523.5 -292,-1133.5 3713,-1133.5 6310,-1133.5 6310,-523.5 -291.5,-523.5 -291.5,-1133.5 1284,-1133.5 ; 2173,-1133.5 2173,-523.5 ; 3440,-726.83 3440,-523.5 ; 4280,-726.83 4280,-523.5 ; 4902,-1140 4902,-937.17
  text "ALL ARTWORK VIEWED FROM TOP SIDE" at -228.5,-655.67 h60
  text "BOARD #:" at 2248,-655.67 h60
  text ".PRJ_Number" at 2793.5,-655.67 h60
  text "REV:" at 3638,-655.67 h60
  text ".PCB_Rev" at 3929.5,-655.67 h60
  text "SVN REV:" at 4476,-655.67 h60
  text ".VersionControl_RevNumber" at 4982,-655.67 h60
  text "LAYER NAME =" at -228.5,-858.49 h60
  text "TID #:" at 2248,-859 h60
  text ".TID" at 2793.5,-859 h60
  text "PLOT NAME =" at -228.5,-1064.34 h60
  text ".plot_File_Name" at 577,-1064.34 h60
  text "GENERATED    :" at 2250,-1064.34 h60
  text ".Print_Date" at 3119.5,-1064.34 h60
  text ".Print_Time" at 3848.5,-1064.34 h60
  text "TEXAS INSTRUMENTS" at 5113,-1064.34 h60
M12 Stackup:
  drawing of 295 lines, arcs and shapes, not listed
  text "Layer" at 6140.34,6228.5 h60
  text "Name" at 6550.26,6228.5 h60
  text "Material" at 7480,6228.5 h60
  text "Thickness" at 8339.77,6228.5 h60
  text "Constant" at 8989.6,6228.5 h60
  text "Board Layer Stack" at 9559.46,6228.5 h60
  text "1" at 6140.34,6108.5 h60
  text "Top Overlay" at 6550.26,6108.5 h60
  text "2" at 6140.34,5988.5 h60
  text "Top Solder" at 6550.26,5988.5 h60
  text "Solder Resist" at 7480,5988.5 h60
  text "0.40mil" at 8339.77,5988.5 h60
  text "3.5" at 8989.6,5988.5 h60
  text "3" at 6140.34,5868.5 h60
  text "Top Layer" at 6550.26,5868.5 h60
  text "Copper" at 7480,5868.5 h60
  text "1.40mil" at 8339.77,5868.5 h60
  text "4" at 6140.34,5748.5 h60
  text "Dielectric 2" at 6550.26,5748.5 h60
  text "FR-4" at 7480,5748.5 h60
  text "19.69mil" at 8339.77,5748.5 h60
  text "4.2" at 8989.6,5748.5 h60
  text "5" at 6140.34,5628.5 h60
  text "Power" at 6550.26,5628.5 h60
  text "Copper" at 7480,5628.5 h60
  text "1.42mil" at 8339.77,5628.5 h60
  text "6" at 6140.34,5508.5 h60
  text "Dielectric1" at 6550.26,5508.5 h60
  text "FR-4" at 7480,5508.5 h60
  text "59.20mil" at 8339.77,5508.5 h60
  text "4.8" at 8989.6,5508.5 h60
  text "7" at 6140.34,5388.5 h60
  text "Ground" at 6550.26,5388.5 h60
  text "Copper" at 7480,5388.5 h60
  text "1.42mil" at 8339.77,5388.5 h60
  text "8" at 6140.34,5268.5 h60
  text "Dielectric 3" at 6550.26,5268.5 h60
  text "FR-4" at 7480,5268.5 h60
  text "19.69mil" at 8339.77,5268.5 h60
  text "4.2" at 8989.6,5268.5 h60
  text "9" at 6140.34,5148.5 h60
  text "Bottom Layer" at 6550.26,5148.5 h60
  text "Copper" at 7480,5148.5 h60
  text "1.40mil" at 8339.77,5148.5 h60
  text "10" at 6140.34,5028.5 h60
  text "Bottom Solder" at 6550.26,5028.5 h60
  text "Solder Resist" at 7480,5028.5 h60
  text "0.40mil" at 8339.77,5028.5 h60
  text "3.5" at 8989.6,5028.5 h60
  text "11" at 6140.34,4908.5 h60
  text "Bottom Overlay" at 6550.26,4908.5 h60
  text ".Layer_Name" at 577,-858.49 h60
M13 Component Bodies Top:
  text ".Layer_Name" at 577,-858.49 h60
M14 Component Bodies Bottom:
  text ".Layer_Name" at 577,-858.49 h60
M15 Courtyards Top:
  text ".Layer_Name" at 577,-858.49 h60
M16 Courtyards Bottom:
  text ".Layer_Name" at 577,-858.49 h60
Drill Drawing:
  circle w10: c6363.72,4051 r27.63
  lines w10: 6336.09,3899.06 6336.09,3912.87 6349.9,3926.68 6336.09,3940.5 6336.09,3954.31 6349.9,3954.31 6363.72,3940.5 6377.53,3954.31 6391.34,3954.31 6391.34,3940.5 6377.53,3926.68 6391.34,3912.87 6391.34,3899.06 6377.53,3899.06 6363.72,3912.87 6349.9,3899.06 6336.09,3899.06 ; 6336.09,4161.51 6349.9,4161.51 6363.72,4147.7 6377.53,4161.51 6391.34,4161.51 6377.53,4175.32 6391.34,4189.14 6377.53,4189.14 6363.72,4202.95 6349.9,4189.14 6336.09,4189.14 6349.9,4175.32 6336.09,4161.51 ; 6336.09,4272.02 6391.34,4272.02 6391.34,4327.27 6336.09,4327.27 6336.09,4272.02 ; 6336.09,4396.34 6363.72,4410.15 6391.34,4396.34 6377.53,4423.96 6391.34,4451.59 6363.72,4437.78 6336.09,4451.59 6349.9,4423.96 6336.09,4396.34 ; 6336.09,4575.91 6391.34,4575.91 6363.72,4520.66 6336.09,4575.91
  lines w12: 6286,3861.76 9517.49,3861.76 ; 6286,4607.68 9517.49,4607.68 ; 6623.86,3737.44 6623.86,4732 ; 6955.86,3737.44 6955.86,4732 ; 7592.43,3737.44 7592.43,4732 ; 7851.57,3737.44 7851.57,4732 ; 8226.72,3737.44 8226.72,4732 ; 8951.05,3737.44 8951.05,4732 ; 6286,3737.44 9517.49,3737.44 9517.49,4732 6286,4732 6286,3737.44
  text "Symbol" at 6360.59,4644.98 h72
  text "Quantity" at 6661.16,4644.98 h72
  text "Finished Hole Size" at 6993.16,4644.98 h72
  text "Plated" at 7629.72,4644.98 h72
  text "Hole Type" at 7888.86,4644.98 h72
  text "Drill Layer Pair" at 8264.02,4644.98 h72
  text "Hole Tolerance" at 8988.35,4644.98 h72
  text "617" at 6661.16,4520.66 h60
  text "9.00mil (0.229mm)" at 6993.16,4520.66 h60
  text "PTH" at 7629.72,4520.66 h60
  text "Round" at 7888.86,4520.66 h60
  text "Top Layer - Bottom Layer" at 8264.02,4520.66 h60
  text "66" at 6661.16,4396.34 h60
  text "10.00mil (0.254mm)" at 6993.16,4396.34 h60
  text "PTH" at 7629.72,4396.34 h60
  text "Round" at 7888.86,4396.34 h60
  text "Top Layer - Bottom Layer" at 8264.02,4396.34 h60
  text "2" at 6661.16,4272.02 h60
  text "39.37mil (1.000mm)" at 6993.16,4272.02 h60
  text "PTH" at 7629.72,4272.02 h60
  text "Round" at 7888.86,4272.02 h60
  text "Top Layer - Bottom Layer" at 8264.02,4272.02 h60
  text "24" at 6661.16,4147.7 h60
  text "40.00mil (1.016mm)" at 6993.16,4147.7 h60
  text "PTH" at 7629.72,4147.7 h60
  text "Round" at 7888.86,4147.7 h60
  text "Top Layer - Bottom Layer" at 8264.02,4147.7 h60
  text "56" at 6661.16,4023.38 h60
  text "40.16mil (1.020mm)" at 6993.16,4023.38 h60
  text "PTH" at 7629.72,4023.38 h60
  text "Round" at 7888.86,4023.38 h60
  text "Top Layer - Bottom Layer" at 8264.02,4023.38 h60
  text "6" at 6661.16,3899.06 h60
  text "40.16mil (1.020mm)" at 6993.16,3899.06 h60
  text "PTH" at 7629.72,3899.06 h60
  text "Round" at 7888.86,3899.06 h60
  text "Top Layer - Bottom Layer" at 8264.02,3899.06 h60
  text "+/-1.97mil" at 8988.35,3899.06 h60
  text "771 Total" at 6661.16,3774.74 h60
  text ".Layer_Name" at 577,-858.49 h60
M17 Embedded Cavity:
  text ".Layer_Name" at 577,-858.49 h60
M18 Embedded Assembly:
  text ".Layer_Name" at 577,-858.49 h60
M19 Embedded Keepout:
  text ".Layer_Name" at 577,-858.49 h60

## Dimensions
0,-400 to 1000,-400 on M2 Board Dimensions
0,2850 to 6245,0 on M2 Board Dimensions
6245,0 to 0,2850 on M2 Board Dimensions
